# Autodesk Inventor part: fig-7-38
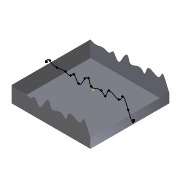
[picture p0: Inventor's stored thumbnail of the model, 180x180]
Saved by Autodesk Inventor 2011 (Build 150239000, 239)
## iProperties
Shininess: 64.0
Length Units: 11269
Angle Units: 11279
Time Units: 11290
Mass Units: 11283
Length Display Precision: 3
Angle Display Precision: 2
Compacted: True
Part Number: fig-7-38
Document SubType Name: Modeling
Created: 2002-12
Designer: deepak
Density: 1 g/cm^3
Density: 0.0
Volumn: 0.0
Area: 0.0
PropertySet Name: Model Information
Control State: 0
Master: False
Checked Out: False
Author: deepak
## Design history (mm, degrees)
sketch "Sketch1"
  geometry: L1 (-32.188, 30.089)-(27.812, 30.089); L2 (27.812, 30.089)-(27.812, -29.911); L3 (27.812, -29.911)-(-32.188, -29.911); L4 (-32.188, -29.911)-(-32.188, 30.089)
  constraints: 8 end point, 2 parallel, 1 horizontal, 1 perpendicular
  dimensions: "d0" = 60 distance of L1.start L1.end; "d1" = 60 distance of L3.end L1.start
extrude "Extrusion1" new body sketch "Sketch1" stored distance "d2" = 20; taper "d3" = 0 deg
sketch "Sketch2"
  geometry: 17 further points
  constraints: 17 other
extrude_surface "ExtrusionSrf1" sketch "Sketch2" dims "d4" = 70, "d5" = 0
split "Split1"
delete_face "Delete Face1"
node "Sketch5"
sketch "Sketch6"
  geometry: 1 further point
body "Srf1"
body "Srf2"
